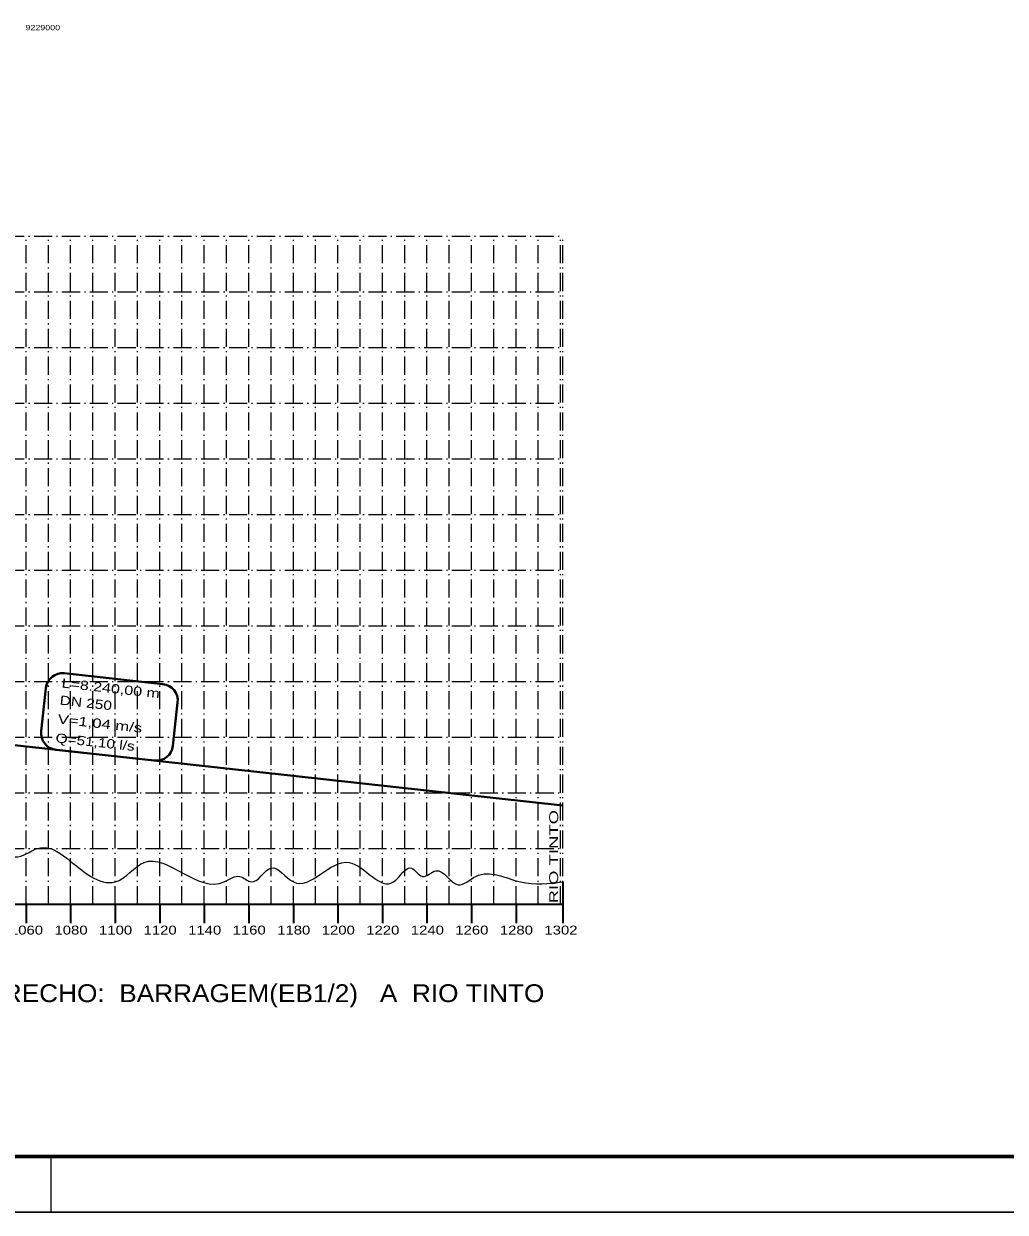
# Model space of a CAD drawing. Extents: x 0 to 1682, y 0 to 1188.
# Drawn here: x 951.9 to 1304.5, y -0.1 to 426.8 of the extents above; entities that cross this region are included whole.
import ezdxf
from ezdxf.enums import TextEntityAlignment as Align

# ---------------------------------------------------------------- set-up
doc = ezdxf.new("R2010")
doc.units = 0
doc.header["$LTSCALE"] = 1.3
doc.linetypes.add('DOT_DASHED', pattern=[7.7, 5, -1.2, 0.3, -1.2])
for name, color, linetype, lineweight in [('1', 7, 'DOT_DASHED', 13), ('56', 7, 'Continuous', 13), ('62', 7, 'Continuous', 13), ('63', 7, 'Continuous', 25), ('9', 7, 'Continuous', 40)]:
    doc.layers.add(name, color=color, linetype=linetype, lineweight=lineweight)
doc.layers.add('24', color=7, linetype='Continuous')

msp = doc.modelspace()

# ---------------------------------------------------------------- linework, layer by layer
at = {"layer": '1'}
for p, q in [((104.775, 350.521), (1145.575, 350.521)), ((952.775, 110.521), (952.775, 350.521)), ((960.775, 110.521), (960.775, 350.521)), ((968.775, 110.521), (968.775, 350.521)), ((976.775, 110.521), (976.775, 350.521)), ((984.775, 110.521), (984.775, 350.521)), ((992.775, 110.521), (992.775, 350.521)), ((1000.775, 110.521), (1000.775, 350.521)), ((1008.775, 110.521), (1008.775, 350.521)), ((1016.775, 110.521), (1016.775, 350.521)), ((1024.775, 110.521), (1024.775, 350.521)), ((1032.775, 110.521), (1032.775, 350.521)), ((1040.775, 110.521), (1040.775, 350.521)), ((1048.775, 110.521), (1048.775, 350.521)), ((1056.775, 110.521), (1056.775, 350.521)), ((1064.775, 110.521), (1064.775, 350.521)), ((1072.775, 110.521), (1072.775, 350.521)), ((1080.775, 110.521), (1080.775, 350.521)), ((1088.775, 110.521), (1088.775, 350.521)), ((1096.775, 110.521), (1096.775, 350.521)), ((1104.775, 110.521), (1104.775, 350.521)), ((1112.775, 110.521), (1112.775, 350.521)), ((1120.775, 110.521), (1120.775, 350.521)), ((1128.775, 110.521), (1128.775, 350.521)), ((1136.775, 110.521), (1136.775, 350.521)), ((1144.775, 110.521), (1144.775, 350.521)), ((1145.575, 110.521), (1145.575, 350.521)), ((104.775, 330.521), (1145.575, 330.521)), ((104.775, 310.521), (1145.575, 310.521)), ((104.775, 290.521), (1145.575, 290.521)), ((104.775, 270.521), (1145.575, 270.521)), ((104.775, 250.521), (1145.575, 250.521)), ((104.775, 230.521), (1145.575, 230.521)), ((104.775, 210.521), (1145.575, 210.521)), ((104.775, 190.521), (1145.575, 190.521)), ((104.775, 170.521), (1145.575, 170.521)), ((104.775, 150.521), (1145.575, 150.521)), ((104.775, 130.521), (1145.575, 130.521))]:
    msp.add_line(p, q, dxfattribs=at)
at = {"layer": '56'}
msp.add_spline([(104.775, 155.521), (114.375, 150.521), (116.375, 145.521), (117.875, 149.271), (119.975, 160.521), (121.575, 150.521), (123.175, 160.521), (127.975, 170.521), (132.775, 183.521), (136.775, 170.521), (139.175, 155.521), (149.575, 188.521), (177.575, 175.521), (202.375, 180.521), (205.575, 178.521), (209.575, 180.521), (213.575, 183.521), (221.575, 176.521), (229.575, 179.521), (241.575, 175.521), (257.575, 180.521), (273.575, 168.521), (286.375, 190.521), (290.375, 195.521), (303.175, 178.521), (318.375, 190.521), (328.775, 187.521), (340.775, 190.521), (348.775, 180.521), (358.375, 193.521), (366.375, 184.521), (376.775, 200.521), (397.575, 190.521), (415.975, 202.521), (446.375, 175.521), (458.375, 185.521), (463.175, 180.521), (475.975, 181.521), (499.975, 149.521), (508.375, 153.521), (524.375, 150.521), (541.975, 165.521), (561.975, 191.521), (569.975, 180.521), (617.975, 143.521), (647.575, 180.521), (655.975, 185.521), (758.375, 160.521), (767.975, 148.521), (774.375, 155.521), (778.375, 158.521), (790.375, 150.521), (798.375, 156.521), (802.375, 150.521), (818.375, 150.521), (858.375, 140.521), (874.375, 128.521), (898.375, 160.521), (910.375, 145.521), (915.175, 153.521), (935.175, 125.521), (940.775, 130.521), (948.775, 127.521), (956.775, 130.521), (975.975, 120.521), (984.775, 118.521), (995.175, 125.521), (1023.975, 118.521), (1029.575, 120.521), (1033.575, 118.521), (1040.775, 123.521), (1048.775, 118.521), (1068.775, 125.521), (1084.775, 118.521), (1091.175, 123.521), (1095.175, 120.521), (1099.975, 122.521), (1107.975, 117.521), (1114.375, 120.521), (1130.375, 118.521), (1145.575, 118.521)], degree=3, dxfattribs=at)
at = {"layer": '62', "lineweight": 35}
for p, q in [((104.775, 110.521), (1145.575, 110.521)), ((952.775, 110.521), (952.775, 103.693)), ((968.775, 110.521), (968.775, 103.693)), ((984.775, 110.521), (984.775, 103.693)), ((1000.775, 110.521), (1000.775, 103.693)), ((1016.775, 110.521), (1016.775, 103.693)), ((1032.775, 110.521), (1032.775, 103.693)), ((1048.775, 110.521), (1048.775, 103.693)), ((1064.775, 110.521), (1064.775, 103.693)), ((1080.775, 110.521), (1080.775, 103.693)), ((1096.775, 110.521), (1096.775, 103.693)), ((1112.775, 110.521), (1112.775, 103.693)), ((1128.775, 110.521), (1128.775, 103.693))]:
    msp.add_line(p, q, dxfattribs=at)
msp.add_lwpolyline([(1145.575, 118.521), (1145.575, 110.521), (1145.575, 103.693)], dxfattribs=at)
at = {"layer": '63', "lineweight": 60}
msp.add_line((1661.832, 19.881), (49.832, 19.881), dxfattribs=at)
at = {"layer": '63'}
msp.add_line((961.832, -0.119), (961.832, 19.881), dxfattribs=at)
for points in [[(-0.168, -0.119), (1681.832, -0.119), (1681.832, 1187.881)], [(-0.168, -0.119), (1681.832, -0.119), (-0.168, -0.119)]]:
    msp.add_lwpolyline(points, dxfattribs=at)
at = {"layer": '9'}
for p, q in [((966.485, 193.464), (1001.906, 189.566)), ((959.865, 188.157), (958.157, 172.64)), ((1007.213, 182.945), (1005.505, 167.429)), ((963.465, 166.02), (998.885, 162.121))]:
    msp.add_line(p, q, dxfattribs=at)
msp.add_lwpolyline([(104.775, 243.105), (148.775, 235.835), (256.775, 225.365), (680.775, 192.657), (816.775, 182.165), (1145.575, 145.975)], dxfattribs=at)
for centre, start, end in [((965.829, 187.5), 83.71891, 173.71891), ((1001.249, 183.602), 353.71891, 83.71891), ((964.121, 171.984), 173.71891, 263.71891), ((999.541, 168.085), 263.71891, 353.71891)]:
    msp.add_arc(centre, 6, start, end, dxfattribs=at)

# ---------------------------------------------------------------- texts
at = {"layer": '24', "width": 1.55}
msp.add_text('RIO TINTO', height=3.2, rotation=90, dxfattribs=at).set_placement((1143.909, 110.828))
at = {"layer": '24'}
for s, height, width, p in [('1060', 3.2, 1.25, (952.915, 99.629)), ('1080', 3.2, 1.25, (968.915, 99.629)), ('1100', 3.2, 1.25, (984.915, 99.629)), ('1120', 3.2, 1.25, (1000.915, 99.629)), ('1140', 3.2, 1.25, (1016.915, 99.629)), ('1160', 3.2, 1.25, (1032.915, 99.629)), ('1180', 3.2, 1.25, (1048.915, 99.629)), ('1200', 3.2, 1.25, (1064.915, 99.629)), ('1220', 3.2, 1.25, (1080.915, 99.629)), ('1240', 3.2, 1.25, (1096.915, 99.629)), ('1260', 3.2, 1.25, (1112.915, 99.629)), ('1280', 3.2, 1.25, (1128.915, 99.629)), ('1302', 3.2, 1.25, (1144.915, 99.629)), ('TRECHO:  BARRAGEM(EB1/2)   A  RIO TINTO', 6.4, 1.1, (1038.803, 75.355))]:
    msp.add_text(s, height=height, dxfattribs=dict(at, width=width)).set_placement(p, align=Align.CENTER)
at = {"layer": '63', "width": 1.25}
msp.add_text('9229000', height=1.911, dxfattribs=at).set_placement((952.549, 424.44))
at = {"layer": '9'}
for s, width, p in [('L=8.240,00 m', 1.3, (965.407, 188.373)), ('DN 250', 1.25, (964.731, 182.231)), ('V=1,04 m/s', 1.35, (963.984, 175.448)), ('Q=51,10 l/s', 1.25, (963.238, 168.665))]:
    msp.add_text(s, height=3.319, rotation=353.719, dxfattribs=dict(at, width=width)).set_placement(p)

doc.saveas('drawing.dxf')
